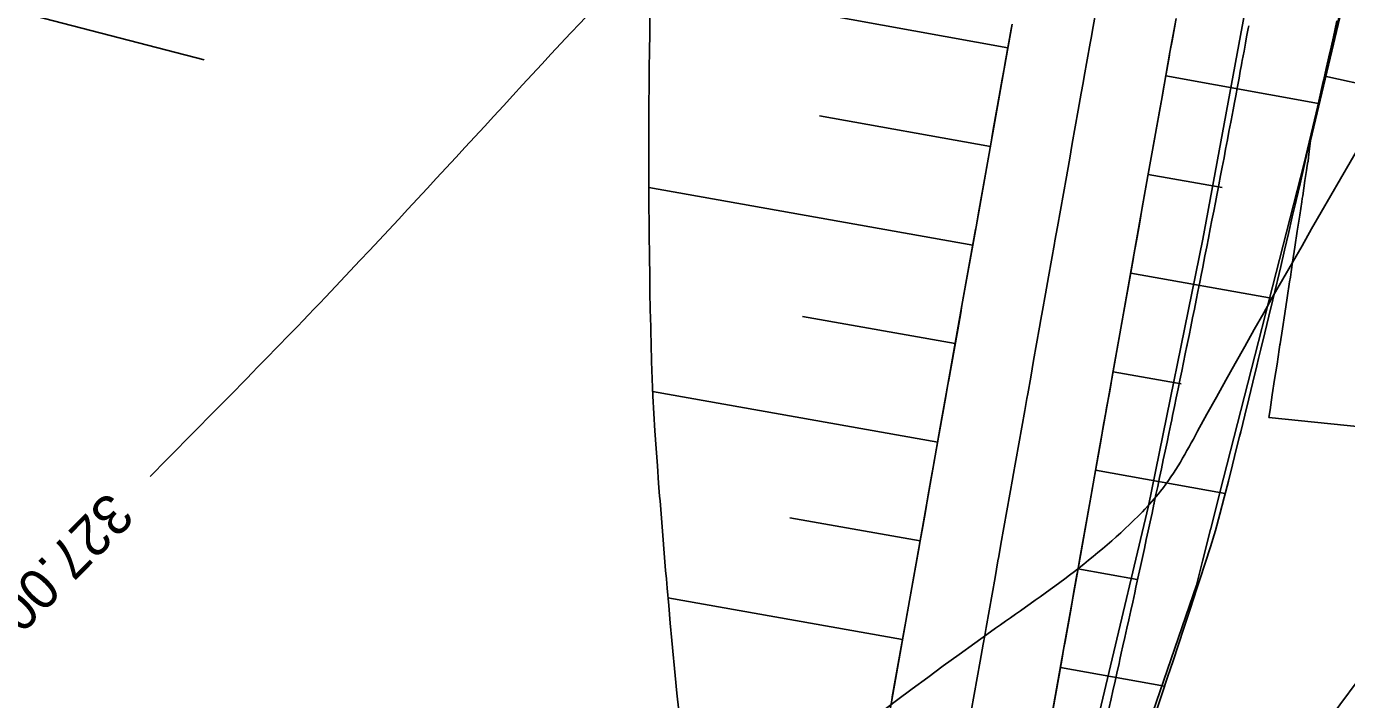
# Model space of a CAD drawing. Extents: x -564037 to -563827, y -1163561 to -1163412.
# Drawn here: x -563942.8 to -563926.34, y -1163495.79 to -1163487.4 of the extents above; entities that cross this region are included whole.
import ezdxf

# ---------------------------------------------------------------- set-up
doc = ezdxf.new("R2010")
doc.units = 0
for name, color, linetype in [('5', 7, 'Continuous'), ('Default', 7, 'Continuous'), ('Line', 7, 'Continuous'), ('Vrstva 24', 7, 'Continuous'), ('Vrstva 25', 7, 'Continuous'), ('Vrstva 26', 7, 'Continuous')]:
    doc.layers.add(name, color=color, linetype=linetype)

msp = doc.modelspace()

# ---------------------------------------------------------------- linework, layer by layer
msp.add_lwpolyline([(-563930.469, -1163501.126), (-563927.863, -1163499.14), (-563925.937, -1163497.674), (-563921.059, -1163495.43), (-563912.613, -1163489.681), (-563911.421, -1163482.517), (-563913.266, -1163479.715), (-563914.137, -1163478.749), (-563916.309, -1163476.467), (-563917.281, -1163475.995), (-563923.761, -1163471.506), (-563924, -1163472.797), (-563925.435, -1163477.844), (-563927.008, -1163483.992), (-563927.659, -1163487.507), (-563928.13, -1163490.05), (-563928.806, -1163493.379), (-563930.34, -1163499.841), (-563930.622, -1163501.15)], close=True)
for points in [[(-563925.566, -1163483.68), (-563926.788, -1163488.822), (-563926.795, -1163488.885), (-563926.811, -1163489.025), (-563926.818, -1163489.08), (-563926.823, -1163489.098), (-563926.825, -1163489.11), (-563926.827, -1163489.131), (-563926.837, -1163489.194), (-563926.856, -1163489.32), (-563926.883, -1163489.509), (-563926.89, -1163489.542), (-563926.896, -1163489.586), (-563926.921, -1163489.749), (-563926.952, -1163489.951), (-563926.981, -1163490.148), (-563927.01, -1163490.339), (-563927.028, -1163490.459), (-563927.038, -1163490.526), (-563927.048, -1163490.584), (-563927.078, -1163490.781), (-563927.108, -1163490.976), (-563927.137, -1163491.167), (-563927.166, -1163491.356), (-563927.168, -1163491.368), (-563927.177, -1163491.426), (-563927.205, -1163491.609), (-563927.235, -1163491.802), (-563927.264, -1163491.992), (-563927.292, -1163492.181), (-563927.306, -1163492.273), (-563922.057, -1163492.813)], [(-563931.018, -1163495.937), (-563930.981, -1163495.729), (-563930.944, -1163495.521), (-563930.907, -1163495.313), (-563930.87, -1163495.104), (-563930.85, -1163494.993), (-563930.833, -1163494.896), (-563930.796, -1163494.688), (-563930.759, -1163494.479), (-563930.722, -1163494.271), (-563930.685, -1163494.063), (-563930.675, -1163494.008), (-563930.648, -1163493.854), (-563930.611, -1163493.646), (-563930.573, -1163493.438), (-563930.536, -1163493.23), (-563930.5, -1163493.024), (-563930.499, -1163493.021), (-563930.462, -1163492.813), (-563930.425, -1163492.605), (-563930.388, -1163492.396), (-563930.351, -1163492.188), (-563930.325, -1163492.039), (-563930.314, -1163491.98), (-563930.277, -1163491.771), (-563930.24, -1163491.563), (-563930.203, -1163491.355), (-563930.166, -1163491.147), (-563930.149, -1163491.054), (-563930.129, -1163490.938), (-563930.092, -1163490.73), (-563930.055, -1163490.522), (-563930.018, -1163490.313), (-563929.98, -1163490.105), (-563929.974, -1163490.07), (-563929.943, -1163489.897), (-563929.906, -1163489.688), (-563929.869, -1163489.48), (-563929.832, -1163489.272), (-563929.799, -1163489.085), (-563929.795, -1163489.064), (-563929.758, -1163488.855), (-563929.721, -1163488.647), (-563929.684, -1163488.439), (-563929.647, -1163488.23), (-563929.624, -1163488.101), (-563929.61, -1163488.022), (-563929.573, -1163487.814), (-563929.536, -1163487.605), (-563929.524, -1163487.542), (-563929.499, -1163487.397), (-563929.461, -1163487.189)], [(-563934.666, -1163495.933), (-563934.689, -1163495.714), (-563934.71, -1163495.495), (-563934.727, -1163495.318), (-563934.731, -1163495.277), (-563934.752, -1163495.058), (-563934.772, -1163494.84), (-563934.792, -1163494.621), (-563934.811, -1163494.403), (-563934.821, -1163494.286), (-563934.83, -1163494.185), (-563934.848, -1163493.967), (-563934.866, -1163493.749), (-563934.883, -1163493.531), (-563934.9, -1163493.313), (-563934.905, -1163493.255), (-563934.917, -1163493.095), (-563934.932, -1163492.877), (-563934.948, -1163492.66), (-563934.963, -1163492.442), (-563934.977, -1163492.227), (-563934.977, -1163492.225), (-563934.991, -1163492.007), (-563934.999, -1163491.791), (-563935.006, -1163491.575), (-563935.011, -1163491.359), (-563935.015, -1163491.204), (-563935.016, -1163491.143), (-563935.021, -1163490.927), (-563935.025, -1163490.712), (-563935.029, -1163490.496), (-563935.032, -1163490.281), (-563935.033, -1163490.185), (-563935.035, -1163490.065), (-563935.037, -1163489.85), (-563935.039, -1163489.635), (-563935.04, -1163489.42), (-563935.041, -1163489.205), (-563935.041, -1163489.168), (-563935.041, -1163488.99), (-563935.041, -1163488.775), (-563935.04, -1163488.56), (-563935.039, -1163488.345), (-563935.037, -1163488.153), (-563935.037, -1163488.131), (-563935.035, -1163487.916), (-563935.032, -1163487.702), (-563935.029, -1163487.488), (-563935.026, -1163487.273)], [(-563933.189, -1163502.428), (-563933.061, -1163501.709), (-563932.976, -1163501.232), (-563932.886, -1163500.725), (-563932.71, -1163499.74), (-563932.535, -1163498.756), (-563932.36, -1163497.771), (-563932.185, -1163496.786), (-563932.01, -1163495.802), (-563931.835, -1163494.817), (-563931.659, -1163493.833), (-563931.484, -1163492.848), (-563931.404, -1163492.395), (-563931.309, -1163491.864), (-563931.134, -1163490.879), (-563930.959, -1163489.895), (-563930.784, -1163488.91), (-563930.608, -1163487.926), (-563930.509, -1163487.367)], [(-563932.01, -1163495.802), (-563932.003, -1163495.762), (-563931.966, -1163495.554), (-563931.929, -1163495.346), (-563931.892, -1163495.137), (-563931.855, -1163494.929), (-563931.835, -1163494.817), (-563931.817, -1163494.721), (-563931.78, -1163494.513), (-563931.743, -1163494.304), (-563931.706, -1163494.096), (-563931.669, -1163493.888), (-563931.659, -1163493.833), (-563931.632, -1163493.679), (-563931.595, -1163493.471), (-563931.558, -1163493.263), (-563931.521, -1163493.054), (-563931.484, -1163492.848), (-563931.484, -1163492.846), (-563931.447, -1163492.638), (-563931.41, -1163492.43), (-563931.373, -1163492.221), (-563931.336, -1163492.013), (-563931.309, -1163491.864), (-563931.299, -1163491.805), (-563931.262, -1163491.596), (-563931.224, -1163491.388), (-563931.187, -1163491.18), (-563931.15, -1163490.971), (-563931.134, -1163490.879), (-563931.113, -1163490.763), (-563931.076, -1163490.555), (-563931.039, -1163490.347), (-563931.002, -1163490.138), (-563930.965, -1163489.93), (-563930.959, -1163489.895), (-563930.928, -1163489.722), (-563930.891, -1163489.513), (-563930.854, -1163489.305), (-563930.817, -1163489.097), (-563930.784, -1163488.91), (-563930.78, -1163488.888), (-563930.743, -1163488.68), (-563930.706, -1163488.472), (-563930.669, -1163488.264), (-563930.631, -1163488.055), (-563930.608, -1163487.926), (-563930.594, -1163487.847), (-563930.557, -1163487.639), (-563930.52, -1163487.43), (-563930.509, -1163487.367)], [(-563932.01, -1163495.802), (-563932.003, -1163495.762), (-563931.966, -1163495.554), (-563931.929, -1163495.346), (-563931.892, -1163495.137), (-563931.855, -1163494.929), (-563931.835, -1163494.817), (-563931.817, -1163494.721), (-563931.78, -1163494.513), (-563931.743, -1163494.304), (-563931.706, -1163494.096), (-563931.669, -1163493.888), (-563931.659, -1163493.833), (-563931.632, -1163493.679), (-563931.595, -1163493.471), (-563931.558, -1163493.263), (-563931.521, -1163493.054), (-563931.484, -1163492.848), (-563931.484, -1163492.846), (-563931.447, -1163492.638), (-563931.41, -1163492.43), (-563931.373, -1163492.221), (-563931.336, -1163492.013), (-563931.309, -1163491.864), (-563931.299, -1163491.805), (-563931.262, -1163491.596), (-563931.224, -1163491.388), (-563931.187, -1163491.18), (-563931.15, -1163490.971), (-563931.134, -1163490.879), (-563931.113, -1163490.763), (-563931.076, -1163490.555), (-563931.039, -1163490.347), (-563931.002, -1163490.138), (-563930.965, -1163489.93), (-563930.959, -1163489.895), (-563930.928, -1163489.722), (-563930.891, -1163489.513), (-563930.854, -1163489.305), (-563930.817, -1163489.097), (-563930.784, -1163488.91), (-563930.78, -1163488.888), (-563930.743, -1163488.68), (-563930.706, -1163488.472), (-563930.669, -1163488.264), (-563930.631, -1163488.055), (-563930.608, -1163487.926), (-563930.594, -1163487.847), (-563930.557, -1163487.639), (-563930.52, -1163487.43), (-563930.509, -1163487.367)], [(-563931.22, -1163502.778), (-563931.092, -1163502.06), (-563931.007, -1163501.582), (-563930.917, -1163501.075), (-563930.741, -1163500.09), (-563930.566, -1163499.106), (-563930.391, -1163498.121), (-563930.216, -1163497.137), (-563930.041, -1163496.152), (-563929.866, -1163495.168), (-563929.69, -1163494.183), (-563929.515, -1163493.199), (-563929.435, -1163492.745), (-563929.34, -1163492.214), (-563929.165, -1163491.23), (-563928.99, -1163490.245), (-563928.815, -1163489.261), (-563928.639, -1163488.276), (-563928.54, -1163487.717), (-563928.464, -1163487.297)], [(-563929.997, -1163495.904), (-563929.96, -1163495.696), (-563929.922, -1163495.488), (-563929.885, -1163495.279), (-563929.866, -1163495.168), (-563929.848, -1163495.071), (-563929.811, -1163494.863), (-563929.774, -1163494.655), (-563929.737, -1163494.446), (-563929.7, -1163494.238), (-563929.69, -1163494.183), (-563929.663, -1163494.03), (-563929.626, -1163493.821), (-563929.589, -1163493.613), (-563929.552, -1163493.405), (-563929.515, -1163493.199), (-563929.515, -1163493.196), (-563929.478, -1163492.988), (-563929.441, -1163492.78), (-563929.404, -1163492.572), (-563929.367, -1163492.363), (-563929.34, -1163492.214), (-563929.33, -1163492.155), (-563929.292, -1163491.947), (-563929.255, -1163491.738), (-563929.218, -1163491.53), (-563929.181, -1163491.322), (-563929.165, -1163491.23), (-563929.144, -1163491.113), (-563929.107, -1163490.905), (-563929.07, -1163490.697), (-563929.033, -1163490.489), (-563928.996, -1163490.28), (-563928.99, -1163490.245), (-563928.959, -1163490.072), (-563928.922, -1163489.864), (-563928.885, -1163489.655), (-563928.848, -1163489.447), (-563928.815, -1163489.261), (-563928.811, -1163489.239), (-563928.774, -1163489.03), (-563928.737, -1163488.822), (-563928.699, -1163488.614), (-563928.662, -1163488.406), (-563928.639, -1163488.276), (-563928.625, -1163488.197), (-563928.588, -1163487.989), (-563928.551, -1163487.781), (-563928.54, -1163487.717), (-563928.514, -1163487.574), (-563928.477, -1163487.369)], [(-563929.997, -1163495.904), (-563929.96, -1163495.696), (-563929.922, -1163495.488), (-563929.885, -1163495.279), (-563929.866, -1163495.168), (-563929.848, -1163495.071), (-563929.811, -1163494.863), (-563929.774, -1163494.655), (-563929.737, -1163494.446), (-563929.7, -1163494.238), (-563929.69, -1163494.183), (-563929.663, -1163494.03), (-563929.626, -1163493.821), (-563929.589, -1163493.613), (-563929.552, -1163493.405), (-563929.515, -1163493.199), (-563929.515, -1163493.196), (-563929.478, -1163492.988), (-563929.441, -1163492.78), (-563929.404, -1163492.572), (-563929.367, -1163492.363), (-563929.34, -1163492.214), (-563929.33, -1163492.155), (-563929.292, -1163491.947), (-563929.255, -1163491.738), (-563929.218, -1163491.53), (-563929.181, -1163491.322), (-563929.165, -1163491.23), (-563929.144, -1163491.113), (-563929.107, -1163490.905), (-563929.07, -1163490.697), (-563929.033, -1163490.489), (-563928.996, -1163490.28), (-563928.99, -1163490.245), (-563928.959, -1163490.072), (-563928.922, -1163489.864), (-563928.885, -1163489.655), (-563928.848, -1163489.447), (-563928.815, -1163489.261), (-563928.811, -1163489.239), (-563928.774, -1163489.03), (-563928.737, -1163488.822), (-563928.699, -1163488.614), (-563928.662, -1163488.406), (-563928.639, -1163488.276), (-563928.625, -1163488.197), (-563928.588, -1163487.989), (-563928.551, -1163487.781), (-563928.54, -1163487.717), (-563928.514, -1163487.574), (-563928.477, -1163487.369)], [(-563927.557, -1163487.387), (-563927.564, -1163487.422), (-563927.572, -1163487.463), (-563927.584, -1163487.527), (-563927.598, -1163487.603), (-563927.616, -1163487.703), (-563927.638, -1163487.819), (-563927.643, -1163487.846), (-563927.649, -1163487.877), (-563927.663, -1163487.953), (-563927.679, -1163488.04), (-563927.698, -1163488.144), (-563927.72, -1163488.262), (-563927.736, -1163488.344), (-563927.753, -1163488.436), (-563927.757, -1163488.458), (-563927.762, -1163488.484), (-563927.782, -1163488.589), (-563927.804, -1163488.706), (-563927.824, -1163488.812), (-563927.846, -1163488.928), (-563927.866, -1163489.034), (-563927.888, -1163489.15), (-563927.909, -1163489.256), (-563927.931, -1163489.372), (-563927.935, -1163489.394), (-563927.94, -1163489.418), (-563927.956, -1163489.502), (-563927.974, -1163489.593), (-563927.994, -1163489.7), (-563928.017, -1163489.815), (-563928.038, -1163489.922), (-563928.06, -1163490.037), (-563928.081, -1163490.144), (-563928.104, -1163490.258), (-563928.117, -1163490.327), (-563928.131, -1163490.4), (-563928.139, -1163490.439), (-563928.147, -1163490.48), (-563928.169, -1163490.588), (-563928.192, -1163490.702), (-563928.213, -1163490.81), (-563928.236, -1163490.923), (-563928.258, -1163491.032), (-563928.28, -1163491.145), (-563928.302, -1163491.253), (-563928.325, -1163491.366), (-563928.327, -1163491.373), (-563928.328, -1163491.38), (-563928.349, -1163491.482), (-563928.37, -1163491.587), (-563928.393, -1163491.696), (-563928.416, -1163491.809), (-563928.438, -1163491.918), (-563928.461, -1163492.03), (-563928.484, -1163492.139), (-563928.507, -1163492.251), (-563928.518, -1163492.305), (-563928.53, -1163492.36), (-563928.541, -1163492.416), (-563928.553, -1163492.473), (-563928.576, -1163492.582), (-563928.6, -1163492.694), (-563928.623, -1163492.803), (-563928.646, -1163492.915), (-563928.669, -1163493.025), (-563928.693, -1163493.136), (-563928.715, -1163493.237), (-563928.736, -1163493.339), (-563928.738, -1163493.348), (-563928.74, -1163493.357), (-563928.764, -1163493.467), (-563928.787, -1163493.578), (-563928.811, -1163493.689), (-563928.835, -1163493.799), (-563928.859, -1163493.911), (-563928.883, -1163494.02), (-563928.908, -1163494.133), (-563928.931, -1163494.241), (-563928.94, -1163494.28), (-563928.948, -1163494.317), (-563928.964, -1163494.392), (-563928.979, -1163494.461), (-563929.005, -1163494.577), (-563929.028, -1163494.682), (-563929.054, -1163494.799), (-563929.077, -1163494.903), (-563929.103, -1163495.021), (-563929.126, -1163495.123), (-563929.147, -1163495.215), (-563929.164, -1163495.294), (-563929.17, -1163495.321), (-563929.175, -1163495.344), (-563929.202, -1163495.465), (-563929.225, -1163495.565), (-563929.252, -1163495.687), (-563929.275, -1163495.785), (-563929.303, -1163495.908)], [(-563928.704, -1163495.919), (-563928.637, -1163495.717), (-563928.569, -1163495.514), (-563928.533, -1163495.405), (-563928.501, -1163495.311), (-563928.434, -1163495.108), (-563928.367, -1163494.905), (-563928.3, -1163494.702), (-563928.234, -1163494.499), (-563928.216, -1163494.446), (-563928.167, -1163494.296), (-563928.101, -1163494.093), (-563928.036, -1163493.889), (-563927.972, -1163493.686), (-563927.919, -1163493.483), (-563927.918, -1163493.481), (-563927.864, -1163493.275), (-563927.812, -1163493.07), (-563927.76, -1163492.864), (-563927.709, -1163492.658), (-563927.672, -1163492.511), (-563927.658, -1163492.452), (-563927.607, -1163492.247), (-563927.556, -1163492.041), (-563927.506, -1163491.835), (-563927.456, -1163491.629), (-563927.434, -1163491.538), (-563927.406, -1163491.423), (-563927.356, -1163491.217), (-563927.306, -1163491.011), (-563927.257, -1163490.805), (-563927.208, -1163490.598), (-563927.2, -1163490.564), (-563927.159, -1163490.392), (-563927.111, -1163490.186), (-563927.062, -1163489.98), (-563927.014, -1163489.773), (-563926.971, -1163489.589), (-563926.966, -1163489.567), (-563926.918, -1163489.361), (-563926.871, -1163489.154), (-563926.824, -1163488.948), (-563926.776, -1163488.741), (-563926.747, -1163488.613), (-563926.73, -1163488.535), (-563926.683, -1163488.328), (-563926.637, -1163488.121), (-563926.622, -1163488.058), (-563926.592, -1163487.92), (-563926.547, -1163487.722), (-563926.531, -1163487.653), (-563926.502, -1163487.524), (-563926.457, -1163487.325)], [(-563928.704, -1163495.919), (-563928.637, -1163495.717), (-563928.569, -1163495.514), (-563928.533, -1163495.405), (-563928.501, -1163495.311), (-563928.434, -1163495.108), (-563928.367, -1163494.905), (-563928.3, -1163494.702), (-563928.234, -1163494.499), (-563928.216, -1163494.446), (-563928.167, -1163494.296), (-563928.101, -1163494.093), (-563928.036, -1163493.889), (-563927.972, -1163493.686), (-563927.919, -1163493.483), (-563927.918, -1163493.481), (-563927.864, -1163493.275), (-563927.812, -1163493.07), (-563927.76, -1163492.864), (-563927.709, -1163492.658), (-563927.672, -1163492.511), (-563927.658, -1163492.452), (-563927.607, -1163492.247), (-563927.556, -1163492.041), (-563927.506, -1163491.835), (-563927.456, -1163491.629), (-563927.434, -1163491.538), (-563927.406, -1163491.423), (-563927.356, -1163491.217), (-563927.306, -1163491.011), (-563927.257, -1163490.805), (-563927.208, -1163490.598), (-563927.2, -1163490.564), (-563927.159, -1163490.392), (-563927.111, -1163490.186), (-563927.062, -1163489.98), (-563927.014, -1163489.773), (-563926.971, -1163489.589), (-563926.966, -1163489.567), (-563926.918, -1163489.361), (-563926.871, -1163489.154), (-563926.824, -1163488.948), (-563926.776, -1163488.741), (-563926.747, -1163488.613), (-563926.73, -1163488.535), (-563926.683, -1163488.328), (-563926.637, -1163488.121), (-563926.622, -1163488.058), (-563926.592, -1163487.92), (-563926.547, -1163487.722), (-563926.531, -1163487.653), (-563926.502, -1163487.524), (-563926.457, -1163487.325)]]:
    msp.add_lwpolyline(points)
at = {"layer": '5'}
msp.add_line((-563977.993, -1163478.142), (-563940.586, -1163487.812), dxfattribs=at)
at = {"layer": 'Default'}
msp.add_lwpolyline([(-563925.948, -1163485.244), (-563926.867, -1163489.1), (-563927.916, -1163493.212), (-563928.032, -1163493.665), (-563928.034, -1163493.674), (-563928.134, -1163494.067), (-563928.211, -1163494.367), (-563929.345, -1163497.668), (-563930.401, -1163500.745), (-563930.002, -1163500.645), (-563928.239, -1163500.208), (-563925.246, -1163498.757), (-563920.654, -1163496.532), (-563920.013, -1163496.222), (-563919.971, -1163496.201), (-563919.419, -1163495.832), (-563914.794, -1163492.742), (-563911.305, -1163489.972), (-563911.26, -1163489.446), (-563911.245, -1163489.265), (-563911.055, -1163487.019)], dxfattribs=at)
at = {"layer": 'Line'}
for p, q in [((-563930.561, -1163487.661), (-563935.017, -1163486.855)), ((-563928.592, -1163488.012), (-563926.689, -1163488.356)), ((-563926.609, -1163488.017), (-563921.461, -1163489.159)), ((-563932.909, -1163488.513), (-563930.78, -1163488.892)), ((-563921.461, -1163489.159), (-563929.957, -1163500.634)), ((-563927.889, -1163489.407), (-563928.811, -1163489.242)), ((-563930.999, -1163490.123), (-563935.04, -1163489.404)), ((-563929.03, -1163490.473), (-563927.254, -1163490.789)), ((-563933.122, -1163491.015), (-563931.218, -1163491.353)), ((-563928.399, -1163491.855), (-563929.249, -1163491.704)), ((-563931.437, -1163492.584), (-563934.993, -1163491.951)), ((-563929.468, -1163492.934), (-563927.851, -1163493.222)), ((-563933.281, -1163493.526), (-563931.656, -1163493.815)), ((-563928.949, -1163494.297), (-563929.687, -1163494.165)), ((-563931.875, -1163495.045), (-563934.801, -1163494.525)), ((-563929.906, -1163495.396), (-563928.607, -1163495.627))]:
    msp.add_line(p, q, dxfattribs=at)
at = {"layer": 'Vrstva 24'}
for points in [[(-563941.26, -1163493.011), (-563939.004, -1163490.701), (-563935.168, -1163486.585), (-563933.596, -1163484.774), (-563933.04, -1163483.789), (-563932.447, -1163481.939), (-563932.386, -1163481.578), (-563932.335, -1163479.091), (-563932.359, -1163478.881), (-563932.37, -1163478.699), (-563932.356, -1163477.982), (-563932.286, -1163477.265), (-563932.226, -1163476.548), (-563932.242, -1163475.831), (-563932.273, -1163475.745), (-563932.328, -1163475.651), (-563935.188, -1163471.035), (-563938.348, -1163465.934), (-563938.454, -1163465.786), (-563938.858, -1163465.285), (-563944.231, -1163458.582)], [(-563939.075, -1163507.623), (-563938.225, -1163507.164), (-563937.324, -1163506.641), (-563936.436, -1163506.097), (-563935.549, -1163505.552), (-563934.649, -1163505.03), (-563930.625, -1163502.906), (-563929.451, -1163502.347), (-563928.196, -1163501.635), (-563924.955, -1163499.225), (-563920.602, -1163495.57), (-563920.316, -1163495.267), (-563915.394, -1163488.268), (-563914.823, -1163487.183), (-563914.579, -1163485.87), (-563914.81, -1163484.102), (-563915.208, -1163482.646), (-563915.847, -1163480.252), (-563916.025, -1163479.9), (-563916.675, -1163479.113), (-563917.077, -1163478.648)]]:
    msp.add_spline(points, degree=3, dxfattribs=at)
at = {"layer": 'Vrstva 26'}
for points in [[(-563938.486, -1163500.528), (-563938.463, -1163500.513), (-563937.665, -1163500.022), (-563936.97, -1163499.566), (-563930.777, -1163494.949), (-563928.884, -1163493.45), (-563928.656, -1163493.192), (-563928.195, -1163492.447), (-563924.372, -1163485.735), (-563923.788, -1163484.5), (-563923.604, -1163483.639), (-563923.611, -1163481.604), (-563923.712, -1163481.017), (-563924.518, -1163478.475), (-563924.689, -1163477.919), (-563924.751, -1163477.798), (-563925.518, -1163476.583), (-563926.306, -1163475.384), (-563927.092, -1163474.184), (-563927.851, -1163472.968), (-563928.532, -1163471.813), (-563929.192, -1163470.645), (-563929.849, -1163469.476), (-563930.525, -1163468.317), (-563930.688, -1163468.07), (-563931.156, -1163467.471), (-563931.276, -1163467.321)], [(-563940.525, -1163513.198), (-563938.9, -1163512.504), (-563932.611, -1163509.84), (-563931.885, -1163509.567), (-563930.901, -1163509.188), (-563926.659, -1163507.216), (-563923.334, -1163505.549), (-563921.652, -1163504.643), (-563920.105, -1163503.651), (-563917.012, -1163501.201), (-563913.048, -1163497.944), (-563912.649, -1163497.606), (-563912.385, -1163497.353), (-563911.289, -1163496.159), (-563908.991, -1163493.383), (-563906.775, -1163490.536), (-563906.699, -1163490.433)]]:
    msp.add_spline(points, degree=3, dxfattribs=at)

# ---------------------------------------------------------------- texts
at = {"layer": 'Vrstva 25'}
msp.add_text('327.00', height=0.5, rotation=225.3062, dxfattribs=at).set_placement((-563941.781, -1163493.182))

doc.saveas('drawing.dxf')
